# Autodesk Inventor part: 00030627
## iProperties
Created: 2011-06
Part Number: 00030627
Document SubType Name: Modeling
Designer: Administrator
Density: 1.06 g/cm^3
Material: ABS Plastic
Mass: 1.37106 g
Surface Area: 23.2085 cm^2
Volume: 1.29346 cm^3
Author: Administrator
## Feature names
1. Base1
